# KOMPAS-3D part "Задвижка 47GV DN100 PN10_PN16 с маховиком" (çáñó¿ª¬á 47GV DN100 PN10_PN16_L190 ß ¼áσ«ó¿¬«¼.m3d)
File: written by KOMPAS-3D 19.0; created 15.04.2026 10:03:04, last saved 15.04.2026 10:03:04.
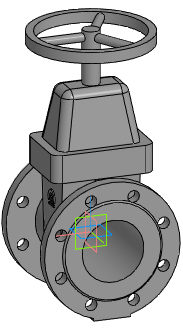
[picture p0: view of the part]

Document properties: Автор: Евгений; Полное имя файла: Z:\3.Личные\kachalov\3d для проектировщиков\2.1 Тип 47GV, 47GV.Z\Задвижка 47GV_DN40-DN600\stp_Задвижка 47GV\Задвижка 47GV DN100 PN10_PN16_L190 с маховиком.m3d

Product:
- Part/product: Задвижка 47GV DN100 PN10_PN16 с маховиком

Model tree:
1. Операция без истории:1  (labels: Задвижка 47GV DN100 PN10_PN16 с маховиком)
